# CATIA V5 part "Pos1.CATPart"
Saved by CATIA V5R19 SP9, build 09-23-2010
Part number: Pos1
Bounding box of the stored display mesh (mm): x 0 to 1000, y -25 to 25, z -50 to 50
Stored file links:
  D:\UG\Beispiel\R19\Produkt_ZSB\Pos1.CATPart
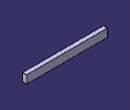
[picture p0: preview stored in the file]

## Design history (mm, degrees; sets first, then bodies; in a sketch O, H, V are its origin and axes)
AxisSystem1: origin (0, 0, 0), X (1, 0, 0), Y (0, 1, 0), Z (0, 0, 1)
Body1 (main body)
  Sketch1 on YZ plane of AxisSystem1, origin (0, 0, 0), H (0, 1, 0), V (0, 0, 1)
    line L1 (-25, 50) -> (25, 50)
    line L2 (25, 50) -> (25, -50)
    line L3 (25, -50) -> (-25, -50)
    line L4 (-25, -50) -> (-25, 50)
    distance L1 L3 = 100
    length L3 = 50
    horizontal: L1 H, L3 H
    vertical: L2 V, L4 V
    symmetry: L4 L2 V, L1 L3 H
  Pad1: profile Sketch1, direction (1, 0, 0), length 1000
